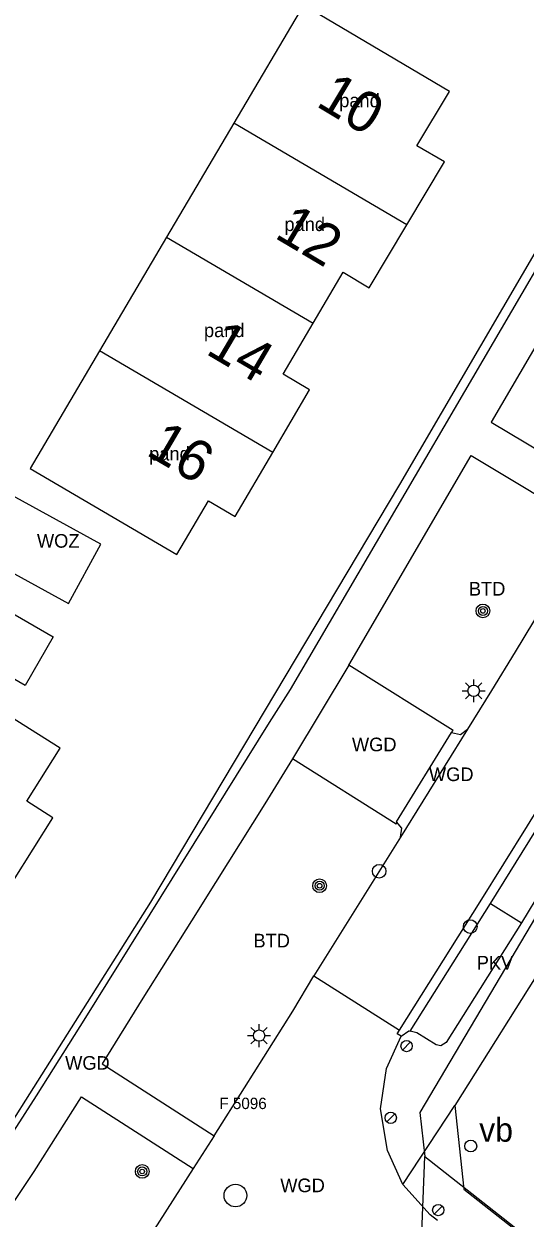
# Model space of a CAD drawing. Extents: x 198240 to 198429, y 356553 to 356721.
# Drawn here: x 198270 to 198292.1, y 356629.6 to 356682.2 of the extents above; entities that cross this region are included whole.
import ezdxf

# ---------------------------------------------------------------- set-up
doc = ezdxf.new("R2010")
doc.units = 0
for name, color, linetype in [('Afsluitpaal', 7, 'Continuous'), ('begroeid terreindeel kenmerkpunt', 7, 'Continuous'), ('BOOM', 7, 'Continuous'), ('grens individueel parkeervak', 7, 'Continuous'), ('Grens maaiveld', 7, 'Continuous'), ('grens WOZ object', 7, 'Continuous'), ('hoofdgebouw', 7, 'Continuous'), ('huisnummerreeks BGT', 7, 'Continuous'), ('identificerend kenmerkpunt pand', 7, 'Continuous'), ('identificerend kenmerkpunt parkeervak', 7, 'Continuous'), ('identificerend kenmerkpunt WOZ object', 7, 'Continuous'), ('Inspectieput_rioolput', 7, 'Continuous'), ('kant verharding', 7, 'Continuous'), ('kolk', 7, 'Continuous'), ('LICHTMAST', 7, 'Continuous'), ('Perceelnummer', 7, 'Continuous'), ('perceelsgrens_definitief', 7, 'Continuous'), ('tussenmuur', 7, 'Continuous'), ('Verkeersbordpaal', 7, 'Continuous'), ('vlakafsluiter', 7, 'Continuous'), ('wegdeel kenmerkpunt', 7, 'Continuous'), ('weginrichtingselement lijn', 7, 'Continuous')]:
    doc.layers.add(name, color=color, linetype=linetype)

msp = doc.modelspace()

# ---------------------------------------------------------------- linework, layer by layer
at = {"layer": 'Afsluitpaal'}
for p, q in [((198287.025, 356637.373), (198286.675, 356637.016)), ((198286.327, 356634.213), (198285.977, 356633.856)), ((198288.418, 356630.153), (198288.068, 356629.796))]:
    msp.add_line(p, q, dxfattribs=at)
for centre in [(198286.852, 356637.193), (198286.154, 356634.033), (198288.245, 356629.973)]:
    msp.add_circle(centre, 0.25, dxfattribs=at)
at = {"layer": 'BOOM'}
for centre, radius in [((198290.207, 356656.348), 0.3), ((198290.207, 356656.348), 0.2), ((198290.207, 356656.348), 0.1), ((198283.023, 356644.251), 0.3), ((198283.023, 356644.251), 0.2), ((198283.023, 356644.251), 0.1), ((198275.221, 356631.674), 0.3), ((198275.221, 356631.674), 0.2), ((198275.221, 356631.674), 0.1)]:
    msp.add_circle(centre, radius, dxfattribs=at)
at = {"layer": 'grens individueel parkeervak'}
msp.add_line((198290.544, 356643.476), (198291.898, 356642.624), dxfattribs=at)
at = {"layer": 'Grens maaiveld'}
for p, q in [((198284.31, 356653.964), (198281.83, 356649.843)), ((198282.777, 356640.29), (198286.537, 356637.898))]:
    msp.add_line(p, q, dxfattribs=at)
for points in [[(198286.537, 356637.898), (198290.083, 356643.54), (198292.172, 356646.883), (198294.288, 356650.332), (198295.232, 356651.912), (198297.381, 356655.439), (198299.42, 356658.858), (198300.465, 356660.59), (198301.471, 356662.302), (198303.507, 356665.731), (198304.495, 356667.459), (198305.49, 356669.172), (198308.283, 356674.098)], [(198286.614, 356637.631), (198286.435, 356637.736), (198286.537, 356637.898)]]:
    msp.add_lwpolyline(points, dxfattribs=at)
at = {"layer": 'grens WOZ object'}
for p, q in [((198273.408, 356659.291), (198269.211, 356661.592)), ((198271.973, 356656.672), (198273.408, 356659.291)), ((198267.776, 356658.973), (198271.973, 356656.672))]:
    msp.add_line(p, q, dxfattribs=at)
msp.add_lwpolyline([(198267.769, 356657.243), (198271.304, 356655.213), (198270.074, 356653.07), (198266.539, 356655.1), (198267.769, 356657.243)], dxfattribs=at)
at = {"layer": 'hoofdgebouw'}
for p, q in [((198279.246, 356677.817), (198276.296, 356672.806)), ((198276.296, 356672.806), (198273.346, 356667.795))]:
    msp.add_line(p, q, dxfattribs=at)
for points in [[(198286.857, 356673.34), (198288.512, 356676.123), (198287.308, 356676.825), (198288.741, 356679.209), (198282.309, 356683.018), (198279.246, 356677.817)], [(198282.743, 356669.013), (198284.065, 356671.256), (198285.208, 356670.566), (198286.857, 356673.34)], [(198280.96, 356663.315), (198282.584, 356666.077), (198281.424, 356666.774), (198282.743, 356669.013)], [(198273.346, 356667.795), (198270.294, 356662.612), (198276.744, 356658.833), (198278.142, 356661.197), (198279.306, 356660.501), (198280.96, 356663.315)], [(198269.556, 356644.485), (198271.294, 356647.246), (198270.143, 356647.981), (198271.619, 356650.308), (198265.328, 356654.273), (198262.114, 356649.176)]]:
    msp.add_lwpolyline(points, dxfattribs=at)
at = {"layer": 'Inspectieput_rioolput'}
msp.add_circle((198279.322, 356630.614), 0.5, dxfattribs=at)
at = {"layer": 'kant verharding'}
for p, q in [((198286.403, 356647.058), (198288.826, 356651.002)), ((198289.527, 356651.142), (198286.577, 356646.389)), ((198286.577, 356646.389), (198282.777, 356640.29)), ((198287.01, 356637.843), (198290.544, 356643.476)), ((198278.38, 356633.246), (198277.462, 356631.806))]:
    msp.add_line(p, q, dxfattribs=at)
for points in [[(198298.672, 356681.879), (198281.729, 356652.893), (198280.805, 356651.439), (198272.725, 356638.444), (198270.553, 356635.006), (198264.327, 356625.306), (198262.967, 356623.203)], [(198299.71, 356680.28), (198290.566, 356664.656), (198295.83, 356661.522)], [(198314.814, 356674.063), (198312.029, 356672.963), (198310.527, 356670.277), (198309.599, 356668.644), (198306.585, 356663.435), (198304.556, 356659.989), (198303.55, 356658.264), (198301.482, 356654.843), (198300.453, 356653.124), (198299.402, 356651.409), (198295.243, 356644.568), (198294.178, 356642.884), (198293.122, 356641.182), (198288.971, 356634.577)], [(198284.31, 356653.964), (198289.691, 356663.193), (198294.945, 356660.041)], [(198294.945, 356660.041), (198291.623, 356654.549), (198290.581, 356652.845), (198289.527, 356651.142)], [(198288.826, 356651.002), (198288.893, 356651.081), (198284.31, 356653.964)], [(198288.826, 356651.002), (198289.223, 356650.905), (198289.527, 356651.142)], [(198281.83, 356649.843), (198280.616, 356647.861), (198278.442, 356644.395), (198277.392, 356642.699), (198275.251, 356639.297), (198273.458, 356636.411), (198278.38, 356633.246)], [(198286.403, 356647.058), (198286.386, 356646.955), (198281.83, 356649.843)], [(198290.544, 356643.476), (198292.54, 356646.68), (198294.317, 356649.594)], [(198295.687, 356648.769), (198293.888, 356645.827), (198292.831, 356644.137), (198291.898, 356642.624)], [(198286.577, 356646.389), (198286.644, 356646.781), (198286.403, 356647.058)], [(198291.898, 356642.624), (198288.59, 356637.357), (198288.351, 356637.209), (198288.152, 356637.242), (198287.305, 356637.782), (198287.01, 356637.843)], [(198278.38, 356633.246), (198279.719, 356635.348), (198281.854, 356638.727), (198282.777, 356640.29)], [(198286.69, 356631.104), (198286.014, 356632.597), (198285.709, 356634.431), (198285.961, 356636.206), (198286.614, 356637.631)], [(198286.614, 356637.631), (198286.944, 356637.857), (198287.01, 356637.843)], [(198265.95, 356624.757), (198268.291, 356628.312), (198269.36, 356629.996), (198270.462, 356631.678), (198272.546, 356634.962), (198277.462, 356631.806)], [(198288.971, 356634.577), (198289.364, 356630.899), (198311.48, 356613.492)], [(198277.462, 356631.806), (198275.413, 356628.597), (198274.312, 356626.921), (198273.106, 356625.127)], [(198288.208, 356629.517), (198287.888, 356629.764), (198286.69, 356631.104)]]:
    msp.add_lwpolyline(points, dxfattribs=at)
at = {"layer": 'kolk'}
for centre in [(198285.644, 356644.888), (198289.651, 356642.454)]:
    msp.add_circle(centre, 0.3, dxfattribs=at)
at = {"layer": 'LICHTMAST'}
for p, q in [((198289.624, 356653.009), (198289.447, 356653.186)), ((198289.801, 356653.082), (198289.801, 356653.332)), ((198289.978, 356653.009), (198290.155, 356653.186)), ((198289.301, 356652.832), (198289.551, 356652.832)), ((198289.447, 356652.478), (198289.624, 356652.655)), ((198289.801, 356652.332), (198289.801, 356652.582)), ((198290.155, 356652.478), (198289.978, 356652.655)), ((198290.051, 356652.832), (198290.301, 356652.832)), ((198280.36, 356637.902), (198280.36, 356638.152)), ((198279.86, 356637.652), (198280.11, 356637.652)), ((198280.183, 356637.829), (198280.006, 356638.006)), ((198280.537, 356637.829), (198280.714, 356638.006)), ((198280.61, 356637.652), (198280.86, 356637.652)), ((198280.006, 356637.298), (198280.183, 356637.475)), ((198280.36, 356637.152), (198280.36, 356637.402)), ((198280.714, 356637.298), (198280.537, 356637.475))]:
    msp.add_line(p, q, dxfattribs=at)
for centre in [(198289.801, 356652.832), (198280.36, 356637.652)]:
    msp.add_circle(centre, 0.25, dxfattribs=at)
at = {"layer": 'perceelsgrens_definitief'}
for points in [[(198243.211, 356592.912), (198264.167, 356625.417), (198275.594, 356643.523), (198286.547, 356661.91), (198298.205, 356681.89)], [(198312.991, 356675.082), (198311.361, 356674.706), (198287.433, 356634.266)], [(198287.433, 356634.266), (198287.646, 356632.339)], [(198287.174, 356620.057), (198287.646, 356632.339)], [(198287.646, 356632.339), (198335.086, 356594.965)]]:
    msp.add_lwpolyline(points, dxfattribs=at)
at = {"layer": 'tussenmuur'}
for p, q in [((198286.857, 356673.34), (198279.246, 356677.817)), ((198276.296, 356672.806), (198282.743, 356669.013)), ((198280.96, 356663.315), (198273.346, 356667.795))]:
    msp.add_line(p, q, dxfattribs=at)
at = {"layer": 'Verkeersbordpaal'}
msp.add_circle((198289.67, 356632.794), 0.263, dxfattribs=at)
at = {"layer": 'vlakafsluiter'}
msp.add_line((198286.69, 356631.104), (198288.971, 356634.577), dxfattribs=at)
at = {"layer": 'weginrichtingselement lijn'}
for points in [[(198286.537, 356637.898), (198290.083, 356643.54), (198292.172, 356646.883), (198294.288, 356650.332), (198295.232, 356651.912), (198297.381, 356655.439), (198299.42, 356658.858), (198300.465, 356660.59), (198301.471, 356662.302), (198303.507, 356665.731), (198304.495, 356667.459), (198305.49, 356669.172), (198308.283, 356674.098)], [(198286.614, 356637.631), (198286.435, 356637.736), (198286.537, 356637.898)]]:
    msp.add_lwpolyline(points, dxfattribs=at)

# ---------------------------------------------------------------- texts
at = {"layer": 'begroeid terreindeel kenmerkpunt'}
for p in [(198289.592, 356657.023), (198280.114, 356641.536)]:
    msp.add_text('BTD', height=0.6, dxfattribs=at).set_placement(p)
at = {"layer": 'huisnummerreeks BGT'}
for s, rotation, p in [('10', 329, (198282.814, 356678.602)), ('12', 329.3, (198280.986, 356672.804)), ('14', 329.5, (198277.963, 356667.693)), ('16', 329.6, (198275.338, 356663.25))]:
    msp.add_text(s, height=1.8, rotation=rotation, dxfattribs=at).set_placement(p)
at = {"layer": 'identificerend kenmerkpunt pand'}
for p in [(198283.888, 356678.52), (198281.478, 356673.07), (198277.938, 356668.4), (198275.528, 356662.97)]:
    msp.add_text('pand', height=0.6, dxfattribs=at).set_placement(p)
at = {"layer": 'identificerend kenmerkpunt parkeervak'}
msp.add_text('PKV', height=0.6, dxfattribs=at).set_placement((198289.935, 356640.563))
at = {"layer": 'identificerend kenmerkpunt WOZ object'}
msp.add_text('WOZ', height=0.6, dxfattribs=at).set_placement((198270.592, 356659.132))
at = {"layer": 'Perceelnummer'}
msp.add_text('F 5096', height=0.5, dxfattribs=at).set_placement((198278.616, 356634.42))
at = {"layer": 'Verkeersbordpaal'}
msp.add_text('vb', height=1.05, dxfattribs=at).set_placement((198290.046, 356632.984))
at = {"layer": 'wegdeel kenmerkpunt'}
for p in [(198284.446, 356650.17), (198287.834, 356648.858), (198271.831, 356636.152), (198281.294, 356630.761)]:
    msp.add_text('WGD', height=0.6, dxfattribs=at).set_placement(p)

doc.saveas('drawing.dxf')
